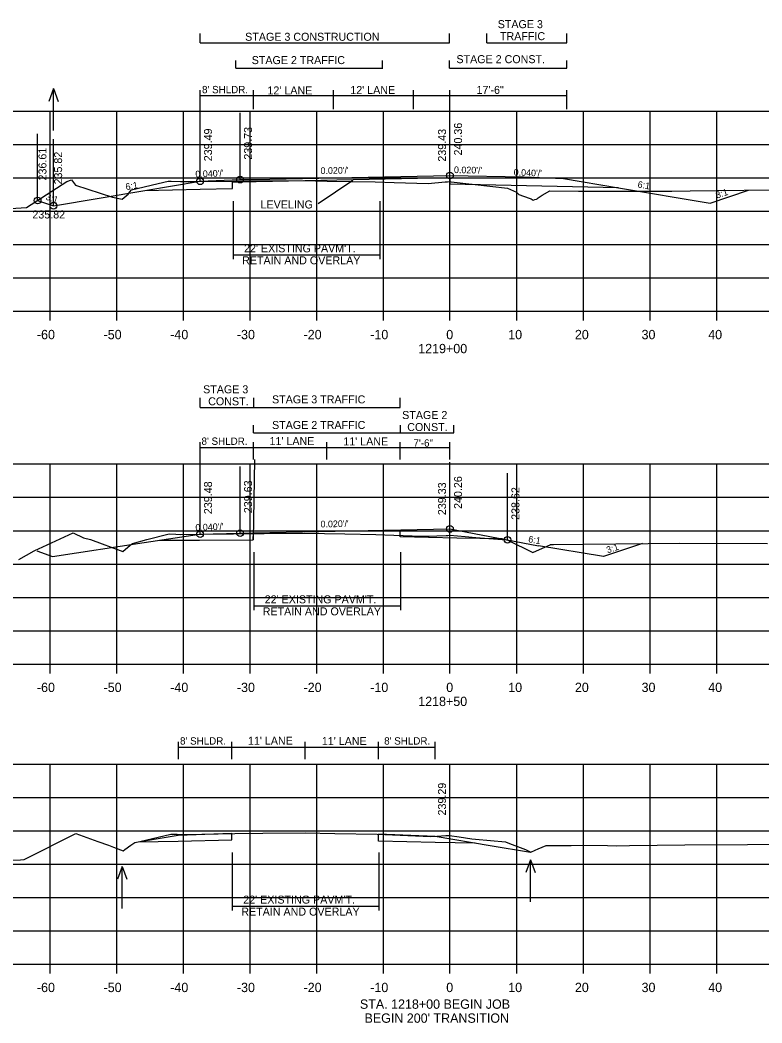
# Model space of a CAD drawing. Extents: x 1342547 to 1344156, y -1532351 to -1517216.
# Drawn here: x 1342638.4 to 1342749.7, y -1532340 to -1532189.6 of the extents above; entities that cross this region are included whole.
import ezdxf

# ---------------------------------------------------------------- set-up
doc = ezdxf.new("R2010")
doc.units = 0
for name, color, linetype in [('R_Alt Surface', 7, 'Continuous'), ('R_Axis', 7, 'Continuous'), ('R_Axis Annot', 7, 'Continuous'), ('R_Draft', 7, 'Continuous'), ('R_Exist Surface', 7, 'Continuous'), ('R_Fin Surface', 7, 'Continuous'), ('R_Grid', 7, 'Continuous'), ('R_No Plot', 7, 'Continuous'), ('R_Water', 7, 'Continuous'), ('R_Water Annot', 7, 'Continuous'), ('R_Xsect Elev', 7, 'Continuous'), ('R_Xsect Slope', 7, 'Continuous')]:
    doc.layers.add(name, color=color, linetype=linetype)

msp = doc.modelspace()

# ---------------------------------------------------------------- linework, layer by layer
at = {"layer": 'R_Alt Surface'}
for p, q in [((1342702.86, -1532213.21), (1342702.86, -1532214.21)), ((1342673.36, -1532267.52), (1342673.37, -1532266.48)), ((1342695.37, -1532267.09), (1342695.37, -1532266.04)), ((1342670.14, -1532312.53), (1342670.14, -1532311.49)), ((1342692.14, -1532312.73), (1342692.14, -1532311.68))]:
    msp.add_line(p, q, dxfattribs=at)
for points in [[(1342670.25, -1532214.86), (1342670.26, -1532213.89), (1342671.37, -1532213.84), (1342702.86, -1532213.21)], [(1342728.14, -1532214.72), (1342702.86, -1532214.21)], [(1342657.09, -1532215.13), (1342665.37, -1532214.96)], [(1342665.37, -1532214.96), (1342670.25, -1532214.86)], [(1342703.87, -1532267.26), (1342695.37, -1532267.09)], [(1342710.76, -1532267.39), (1342703.87, -1532267.26)], [(1342659.28, -1532267.58), (1342665.28, -1532267.56)], [(1342665.28, -1532267.56), (1342673.35, -1532267.52)], [(1342656.07, -1532312.82), (1342662.07, -1532312.7)], [(1342662.07, -1532312.7), (1342670.14, -1532312.53)], [(1342700.64, -1532312.9), (1342692.14, -1532312.73)], [(1342706.63, -1532313.02), (1342700.64, -1532312.9)]]:
    msp.add_lwpolyline(points, dxfattribs=at)
at = {"layer": 'R_Axis'}
for p, q in [((1342562.87, -1532233.24), (1342842.87, -1532233.24)), ((1342642.87, -1532234.64), (1342642.87, -1532233.24)), ((1342652.87, -1532234.64), (1342652.87, -1532233.24)), ((1342662.87, -1532234.64), (1342662.87, -1532233.24)), ((1342672.87, -1532234.64), (1342672.87, -1532233.24)), ((1342682.87, -1532234.64), (1342682.87, -1532233.24)), ((1342692.87, -1532234.64), (1342692.87, -1532233.24)), ((1342702.86, -1532234.64), (1342702.86, -1532233.24)), ((1342712.87, -1532234.64), (1342712.87, -1532233.24)), ((1342722.87, -1532234.64), (1342722.87, -1532233.24)), ((1342732.87, -1532234.64), (1342732.87, -1532233.24)), ((1342742.87, -1532234.64), (1342742.87, -1532233.24)), ((1342562.87, -1532286.15), (1342842.87, -1532286.15)), ((1342642.87, -1532287.55), (1342642.87, -1532286.15)), ((1342652.87, -1532287.55), (1342652.87, -1532286.15)), ((1342662.87, -1532287.55), (1342662.87, -1532286.15)), ((1342672.87, -1532287.55), (1342672.87, -1532286.15)), ((1342682.87, -1532287.55), (1342682.87, -1532286.15)), ((1342692.87, -1532287.55), (1342692.87, -1532286.15)), ((1342702.86, -1532287.55), (1342702.86, -1532286.15)), ((1342712.87, -1532287.55), (1342712.87, -1532286.15)), ((1342722.87, -1532287.55), (1342722.87, -1532286.15)), ((1342732.87, -1532287.55), (1342732.87, -1532286.15)), ((1342742.87, -1532287.55), (1342742.87, -1532286.15)), ((1342562.87, -1532331.15), (1342842.87, -1532331.15)), ((1342642.87, -1532332.55), (1342642.87, -1532331.15)), ((1342652.87, -1532332.55), (1342652.87, -1532331.15)), ((1342662.87, -1532332.55), (1342662.87, -1532331.15)), ((1342672.87, -1532332.55), (1342672.87, -1532331.15)), ((1342682.87, -1532332.55), (1342682.87, -1532331.15)), ((1342692.87, -1532332.55), (1342692.87, -1532331.15)), ((1342702.86, -1532332.55), (1342702.86, -1532331.15)), ((1342712.87, -1532332.55), (1342712.87, -1532331.15)), ((1342722.87, -1532332.55), (1342722.87, -1532331.15)), ((1342732.87, -1532332.55), (1342732.87, -1532331.15)), ((1342742.87, -1532332.55), (1342742.87, -1532331.15))]:
    msp.add_line(p, q, dxfattribs=at)
at = {"layer": 'R_Draft'}
for p, q in [((1342665.37, -1532193.01), (1342665.37, -1532191.58)), ((1342702.78, -1532193.01), (1342702.78, -1532191.58)), ((1342708.37, -1532193.01), (1342708.37, -1532191.58)), ((1342720.37, -1532193.01), (1342720.37, -1532191.58)), ((1342665.37, -1532193.01), (1342702.78, -1532193.01)), ((1342708.37, -1532193.01), (1342720.37, -1532193.01)), ((1342670.72, -1532196.8), (1342670.72, -1532195.66)), ((1342692.72, -1532196.9), (1342692.72, -1532195.66)), ((1342702.78, -1532196.8), (1342702.78, -1532195.66)), ((1342720.37, -1532196.8), (1342720.37, -1532195.66)), ((1342670.72, -1532196.8), (1342692.72, -1532196.8)), ((1342702.78, -1532196.8), (1342720.37, -1532196.8)), ((1342670.33, -1532216.73), (1342670.33, -1532225.45)), ((1342692.33, -1532216.73), (1342692.33, -1532225.45)), ((1342670.33, -1532224.78), (1342692.33, -1532224.78)), ((1342665.37, -1532247.67), (1342665.37, -1532246.24)), ((1342665.37, -1532247.67), (1342695.37, -1532247.67)), ((1342673.37, -1532246.24), (1342673.37, -1532247.67)), ((1342695.37, -1532247.67), (1342695.37, -1532246.24)), ((1342673.37, -1532251.47), (1342673.37, -1532250.33)), ((1342695.37, -1532250.33), (1342695.37, -1532251.47)), ((1342703.42, -1532251.47), (1342703.42, -1532250.33)), ((1342673.37, -1532251.47), (1342692.72, -1532251.47)), ((1342685.84, -1532251.47), (1342703.42, -1532251.47)), ((1342673.42, -1532269.37), (1342673.42, -1532278.09)), ((1342695.43, -1532269.37), (1342695.43, -1532278.09)), ((1342673.42, -1532277.41), (1342695.43, -1532277.41)), ((1342670.21, -1532314.4), (1342670.21, -1532323.12)), ((1342692.21, -1532314.4), (1342692.21, -1532323.12)), ((1342670.21, -1532322.45), (1342692.21, -1532322.45))]:
    msp.add_line(p, q, dxfattribs=at)
at = {"layer": 'R_Exist Surface'}
for points in [[(1342630.56, -1532218.22), (1342639.35, -1532217.69), (1342645.4, -1532213.8), (1342646.08, -1532213.54), (1342646.71, -1532214.35), (1342652.22, -1532216.14), (1342653.69, -1532216.43), (1342654.61, -1532215.7), (1342654.82, -1532215.32), (1342655.11, -1532215.03), (1342659.94, -1532213.91), (1342660.6, -1532213.73), (1342661.04, -1532213.75), (1342662.43, -1532213.8), (1342664.72, -1532213.78), (1342670.26, -1532213.73), (1342673.46, -1532213.71), (1342680.93, -1532213.66), (1342684.43, -1532213.73), (1342691.64, -1532213.85), (1342694.48, -1532213.93), (1342699.59, -1532214.08), (1342702.15, -1532213.86), (1342702.5, -1532213.83), (1342702.85, -1532213.81), (1342703.06, -1532213.83), (1342706.15, -1532214.18), (1342706.21, -1532214.19), (1342711.48, -1532214.78), (1342712.83, -1532215.4), (1342713.2, -1532215.74), (1342714.75, -1532216.28), (1342715.02, -1532216.39), (1342715.35, -1532216.58), (1342715.6, -1532216.46), (1342715.82, -1532216.42), (1342715.94, -1532216.37), (1342716.07, -1532216.22), (1342716.7, -1532215.85), (1342717.82, -1532215.17), (1342722.13, -1532215.24), (1342723.02, -1532215.26), (1342724.92, -1532215.23), (1342736.14, -1532215.22), (1342738.91, -1532215.19), (1342755.04, -1532214.99)], [(1342638.19, -1532270.45), (1342640.47, -1532269.19), (1342646.32, -1532266.45), (1342647.89, -1532267.2), (1342648.93, -1532267.47), (1342653.8, -1532269.26), (1342654.9, -1532268.33), (1342655.22, -1532268.06), (1342657.4, -1532267.49), (1342660.76, -1532266.64), (1342661.76, -1532266.68), (1342662.47, -1532266.71), (1342665.87, -1532266.67), (1342670.38, -1532266.6), (1342674.98, -1532266.57), (1342680.99, -1532266.53), (1342687.1, -1532266.64), (1342691.75, -1532266.72), (1342698.55, -1532266.95), (1342699.74, -1532266.99), (1342700.88, -1532266.93), (1342702.28, -1532266.86), (1342702.52, -1532266.85), (1342702.86, -1532266.82), (1342705.16, -1532267.04), (1342706.73, -1532267.19), (1342711.36, -1532267.52), (1342711.48, -1532267.53), (1342711.55, -1532267.56), (1342715.27, -1532269.44), (1342716.75, -1532268.76), (1342717.88, -1532268.27), (1342717.96, -1532268.22), (1342718.41, -1532268.22), (1342722.84, -1532268.18), (1342732.58, -1532268.07), (1342737.25, -1532268), (1342750.5, -1532268.05)], [(1342629.07, -1532315.88), (1342638.45, -1532315.51), (1342639.01, -1532315.48), (1342639.41, -1532315.27), (1342646.76, -1532311.58), (1342650.04, -1532312.75), (1342651.65, -1532313.31), (1342652.39, -1532313.63), (1342653.82, -1532314.16), (1342654.07, -1532313.94), (1342654.99, -1532313.33), (1342655.6, -1532312.93), (1342656.33, -1532312.76), (1342660.98, -1532311.67), (1342661.93, -1532311.68), (1342662.64, -1532311.71), (1342665.63, -1532311.65), (1342670.58, -1532311.54), (1342674.77, -1532311.51), (1342681.14, -1532311.47), (1342685.57, -1532311.55), (1342691.94, -1532311.67), (1342698.86, -1532311.95), (1342699.98, -1532312), (1342700.89, -1532311.95), (1342702.22, -1532311.88), (1342702.45, -1532311.86), (1342702.8, -1532311.85), (1342704.25, -1532312.06), (1342706.14, -1532312.36), (1342706.68, -1532312.4), (1342711.17, -1532312.79), (1342711.81, -1532313.05), (1342714.18, -1532313.97), (1342714.97, -1532314.37), (1342715.64, -1532314.06), (1342716.11, -1532313.88), (1342717.29, -1532313.36), (1342721.04, -1532313.35), (1342722.78, -1532313.33), (1342726.49, -1532313.37), (1342727.84, -1532313.39), (1342729.77, -1532313.36), (1342738.09, -1532313.27), (1342747.47, -1532313.2), (1342754.83, -1532313.14)]]:
    msp.add_lwpolyline(points, dxfattribs=at)
at = {"layer": 'R_Fin Surface'}
for p, q in [((1342673.37, -1532213.47), (1342702.86, -1532212.88)), ((1342702.86, -1532212.88), (1342713.87, -1532213.1)), ((1342713.87, -1532213.1), (1342719.87, -1532213.34)), ((1342657.09, -1532215.13), (1342665.37, -1532213.75)), ((1342665.37, -1532213.75), (1342671.37, -1532213.51)), ((1342671.37, -1532213.51), (1342673.37, -1532213.47)), ((1342719.87, -1532213.34), (1342728.14, -1532214.72)), ((1342643.37, -1532217.42), (1342657.09, -1532215.13)), ((1342728.14, -1532214.72), (1342741.87, -1532217.01)), ((1342741.87, -1532217.01), (1342747.64, -1532215.08)), ((1342641.01, -1532216.63), (1342643.37, -1532217.42))]:
    msp.add_line(p, q, dxfattribs=at)
for points in [[(1342640.9, -1532269.19), (1342643.24, -1532270.01), (1342657, -1532267.93), (1342665.3, -1532266.68), (1342673.37, -1532266.48)], [(1342665.37, -1532266.67), (1342671.37, -1532266.52), (1342673.37, -1532266.48), (1342702.86, -1532265.89), (1342716.12, -1532268.42)], [(1342731.75, -1532268.08), (1342725.87, -1532270.04), (1342716.12, -1532268.42)], [(1342656.07, -1532312.82), (1342662.07, -1532311.82), (1342670.14, -1532311.49)], [(1342714.96, -1532314.4), (1342708.91, -1532313.4), (1342700.64, -1532312.02), (1342692.14, -1532311.68)]]:
    msp.add_lwpolyline(points, dxfattribs=at)
at = {"layer": 'R_Grid'}
for p, q in [((1342562.87, -1532203.24), (1342842.87, -1532203.24)), ((1342642.87, -1532233.24), (1342642.87, -1532203.24)), ((1342652.87, -1532233.24), (1342652.87, -1532203.24)), ((1342662.87, -1532233.24), (1342662.87, -1532203.24)), ((1342672.87, -1532233.24), (1342672.87, -1532203.24)), ((1342682.87, -1532233.24), (1342682.87, -1532203.24)), ((1342692.87, -1532233.24), (1342692.87, -1532203.24)), ((1342702.86, -1532233.24), (1342702.86, -1532203.24)), ((1342712.87, -1532233.24), (1342712.87, -1532203.24)), ((1342722.87, -1532233.24), (1342722.87, -1532203.24)), ((1342732.87, -1532233.24), (1342732.87, -1532203.24)), ((1342742.87, -1532233.24), (1342742.87, -1532203.24)), ((1342562.87, -1532208.24), (1342842.87, -1532208.24)), ((1342562.87, -1532213.24), (1342842.87, -1532213.24)), ((1342562.87, -1532218.24), (1342842.87, -1532218.24)), ((1342562.87, -1532223.24), (1342842.87, -1532223.24)), ((1342562.87, -1532228.24), (1342842.87, -1532228.24)), ((1342562.87, -1532233.24), (1342842.87, -1532233.24)), ((1342562.87, -1532256.15), (1342842.87, -1532256.15)), ((1342642.87, -1532286.15), (1342642.87, -1532256.15)), ((1342652.87, -1532286.15), (1342652.87, -1532256.15)), ((1342662.87, -1532286.15), (1342662.87, -1532256.15)), ((1342672.87, -1532286.15), (1342672.87, -1532256.15)), ((1342682.87, -1532286.15), (1342682.87, -1532256.15)), ((1342692.87, -1532286.15), (1342692.87, -1532256.15)), ((1342702.86, -1532286.15), (1342702.86, -1532256.15)), ((1342712.87, -1532286.15), (1342712.87, -1532256.15)), ((1342722.87, -1532286.15), (1342722.87, -1532256.15)), ((1342732.87, -1532286.15), (1342732.87, -1532256.15)), ((1342742.87, -1532286.15), (1342742.87, -1532256.15)), ((1342562.87, -1532261.15), (1342842.87, -1532261.15)), ((1342562.87, -1532266.15), (1342842.87, -1532266.15)), ((1342562.87, -1532271.15), (1342842.87, -1532271.15)), ((1342562.87, -1532276.15), (1342842.87, -1532276.15)), ((1342562.87, -1532281.15), (1342842.87, -1532281.15)), ((1342562.87, -1532286.15), (1342842.87, -1532286.15)), ((1342562.87, -1532301.15), (1342842.87, -1532301.15)), ((1342642.87, -1532331.15), (1342642.87, -1532301.15)), ((1342652.87, -1532331.15), (1342652.87, -1532301.15)), ((1342662.87, -1532331.15), (1342662.87, -1532301.15)), ((1342672.87, -1532331.15), (1342672.87, -1532301.15)), ((1342682.87, -1532331.15), (1342682.87, -1532301.15)), ((1342692.87, -1532331.15), (1342692.87, -1532301.15)), ((1342702.86, -1532331.15), (1342702.86, -1532301.15)), ((1342712.87, -1532331.15), (1342712.87, -1532301.15)), ((1342722.87, -1532331.15), (1342722.87, -1532301.15)), ((1342732.87, -1532331.15), (1342732.87, -1532301.15)), ((1342742.87, -1532331.15), (1342742.87, -1532301.15)), ((1342562.87, -1532306.15), (1342842.87, -1532306.15)), ((1342562.87, -1532311.15), (1342842.87, -1532311.15)), ((1342562.87, -1532316.15), (1342842.87, -1532316.15)), ((1342562.87, -1532321.15), (1342842.87, -1532321.15)), ((1342562.87, -1532326.15), (1342842.87, -1532326.15)), ((1342562.87, -1532331.15), (1342842.87, -1532331.15))]:
    msp.add_line(p, q, dxfattribs=at)
at = {"layer": 'R_No Plot'}
for centre in [(1342671.37, -1532213.51), (1342671.37, -1532213.51), (1342702.86, -1532212.88), (1342702.86, -1532212.88), (1342665.37, -1532213.75), (1342665.37, -1532213.75), (1342641.01, -1532216.63), (1342641.01, -1532216.63), (1342643.37, -1532217.42), (1342643.37, -1532217.42), (1342702.86, -1532265.89), (1342702.86, -1532265.89), (1342665.37, -1532266.67), (1342665.37, -1532266.67), (1342671.37, -1532266.52), (1342671.37, -1532266.52), (1342711.48, -1532267.53), (1342711.48, -1532267.53)]:
    msp.add_circle(centre, 0.5, dxfattribs=at)
at = {"layer": 'R_Water'}
for p, q in [((1342643.39, -1532199.85), (1342642.69, -1532201.78)), ((1342643.39, -1532206.14), (1342643.39, -1532199.85)), ((1342643.39, -1532199.85), (1342644.09, -1532201.78)), ((1342653.68, -1532316.51), (1342652.98, -1532318.43)), ((1342653.68, -1532322.79), (1342653.68, -1532316.51)), ((1342653.68, -1532316.51), (1342654.38, -1532318.43)), ((1342714.94, -1532315.51), (1342714.24, -1532317.43)), ((1342714.94, -1532321.79), (1342714.94, -1532315.51)), ((1342714.94, -1532315.51), (1342715.64, -1532317.43))]:
    msp.add_line(p, q, dxfattribs=at)
at = {"layer": 'R_Xsect Elev'}
for p, q in [((1342665.37, -1532213.34), (1342665.37, -1532200.08)), ((1342720.37, -1532200.94), (1342665.37, -1532200.94)), ((1342673.37, -1532202.95), (1342673.37, -1532200.08)), ((1342685.37, -1532202.95), (1342685.37, -1532200.08)), ((1342697.37, -1532202.95), (1342697.37, -1532200.08)), ((1342702.86, -1532202.95), (1342702.86, -1532200.08)), ((1342720.37, -1532202.95), (1342720.37, -1532200.08)), ((1342665.37, -1532213.75), (1342665.37, -1532203.75)), ((1342665.37, -1532213.75), (1342665.37, -1532203.75)), ((1342671.37, -1532213.51), (1342671.37, -1532203.51)), ((1342702.86, -1532212.88), (1342702.86, -1532202.88)), ((1342702.86, -1532213.81), (1342702.86, -1532203.81)), ((1342641.01, -1532216.63), (1342641.01, -1532206.63)), ((1342643.37, -1532217.42), (1342643.37, -1532207.42)), ((1342688.29, -1532213.64), (1342683.09, -1532217.12)), ((1342665.37, -1532266.14), (1342665.37, -1532252.89)), ((1342702.86, -1532253.74), (1342665.37, -1532253.74)), ((1342673.37, -1532255.47), (1342673.37, -1532252.89)), ((1342684.37, -1532255.47), (1342684.37, -1532252.89)), ((1342695.37, -1532255.47), (1342695.37, -1532252.89)), ((1342702.86, -1532255.47), (1342702.86, -1532252.89)), ((1342665.37, -1532266.67), (1342665.37, -1532256.67)), ((1342665.37, -1532266.67), (1342665.37, -1532256.67)), ((1342671.37, -1532266.52), (1342671.37, -1532256.52)), ((1342673.53, -1532255.47), (1342673.35, -1532267.5)), ((1342702.86, -1532265.89), (1342702.86, -1532255.89)), ((1342702.86, -1532266.82), (1342702.86, -1532256.82)), ((1342711.48, -1532267.53), (1342711.48, -1532257.53)), ((1342662.14, -1532300.41), (1342662.14, -1532297.83)), ((1342700.64, -1532298.69), (1342662.14, -1532298.69)), ((1342670.14, -1532300.41), (1342670.14, -1532297.83)), ((1342681.14, -1532300.41), (1342681.14, -1532297.83)), ((1342692.14, -1532300.41), (1342692.14, -1532297.83)), ((1342700.64, -1532300.41), (1342700.64, -1532297.83)), ((1342702.86, -1532311.86), (1342702.86, -1532301.86))]:
    msp.add_line(p, q, dxfattribs=at)

# ---------------------------------------------------------------- texts
at = {"layer": 'R_Axis Annot'}
for s, p in [('-60', (1342640.9, -1532237.44)), ('-50', (1342650.9, -1532237.44)), ('-40', (1342660.9, -1532237.44)), ('-30', (1342670.9, -1532237.44)), ('-20', (1342680.9, -1532237.44)), ('-10', (1342690.9, -1532237.44)), ('0', (1342702.3, -1532237.44)), ('10', (1342711.6, -1532237.44)), ('20', (1342721.6, -1532237.44)), ('30', (1342731.6, -1532237.44)), ('40', (1342741.6, -1532237.44)), ('1219+00', (1342698.1, -1532239.54)), ('-60', (1342640.9, -1532290.35)), ('-50', (1342650.9, -1532290.35)), ('-40', (1342660.9, -1532290.35)), ('-30', (1342670.9, -1532290.35)), ('-20', (1342680.9, -1532290.35)), ('-10', (1342690.9, -1532290.35)), ('0', (1342702.3, -1532290.35)), ('10', (1342711.6, -1532290.35)), ('20', (1342721.6, -1532290.35)), ('30', (1342731.6, -1532290.35)), ('40', (1342741.6, -1532290.35)), ('1218+50', (1342698.1, -1532292.45)), ('-60', (1342640.9, -1532335.35)), ('-50', (1342650.9, -1532335.35)), ('-40', (1342660.9, -1532335.35)), ('-30', (1342670.9, -1532335.35)), ('-20', (1342680.9, -1532335.35)), ('-10', (1342690.9, -1532335.35)), ('0', (1342702.3, -1532335.35)), ('10', (1342711.6, -1532335.35)), ('20', (1342721.6, -1532335.35)), ('30', (1342731.6, -1532335.35)), ('40', (1342741.6, -1532335.35)), ('STA. 1218+00 BEGIN JOB', (1342689.35, -1532337.85)), ("BEGIN 200' TRANSITION", (1342690.04, -1532339.95))]:
    msp.add_text(s, height=1.4, dxfattribs=at).set_placement(p)
at = {"layer": 'R_Draft'}
for s, p in [('STAGE 3', (1342710.02, -1532190.79)), ('STAGE 3 CONSTRUCTION', (1342672.14, -1532192.68)), ('TRAFFIC', (1342710.36, -1532192.59)), ('STAGE 2 TRAFFIC', (1342673.12, -1532196.18)), ('STAGE 2 CONST.', (1342703.83, -1532196.04)), ("22' EXISTING PAVM'T.", (1342671.97, -1532224.41)), ('RETAIN AND OVERLAY', (1342671.68, -1532226.21)), ('STAGE 3', (1342665.83, -1532245.55)), ('CONST.', (1342666.59, -1532247.35)), ('STAGE 3 TRAFFIC', (1342676.17, -1532247.06)), ('STAGE 2', (1342695.69, -1532249.41)), ('STAGE 2 TRAFFIC', (1342676.17, -1532250.9)), ('CONST.', (1342696.45, -1532251.21)), ("22' EXISTING PAVM'T.", (1342675.07, -1532277.05)), ('RETAIN AND OVERLAY', (1342674.77, -1532278.85)), ("22' EXISTING PAVM'T.", (1342671.85, -1532322.08)), ('RETAIN AND OVERLAY', (1342671.56, -1532323.88))]:
    msp.add_text(s, height=1.2, dxfattribs=at).set_placement(p)
at = {"layer": 'R_Water Annot'}
msp.add_text('235.82', height=1.2, dxfattribs=at).set_placement((1342640.22, -1532219.33))
msp.add_text('235.82', height=1.2, dxfattribs=at).set_placement((1342640.22, -1532219.33))
at = {"layer": 'R_Xsect Elev'}
for s, height, p in [("8' SHLDR.", 1.1, (1342665.67, -1532200.55)), ("12' LANE", 1.2, (1342675.48, -1532200.73)), ("12' LANE", 1.2, (1342687.91, -1532200.67)), ('17\'-6"', 1.2, (1342706.84, -1532200.65)), ('LEVELING', 1.2, (1342674.45, -1532217.83)), ("8' SHLDR.", 1.1, (1342665.59, -1532253.28)), ("11' LANE", 1.2, (1342675.79, -1532253.31)), ("11' LANE", 1.2, (1342686.86, -1532253.36)), ('7\'-6"', 1.1, (1342697.38, -1532253.55)), ("8' SHLDR.", 1.1, (1342662.37, -1532298.23)), ("11' LANE", 1.2, (1342672.56, -1532298.25)), ("11' LANE", 1.2, (1342683.64, -1532298.3)), ("8' SHLDR.", 1.1, (1342692.99, -1532298.23))]:
    msp.add_text(s, height=height, dxfattribs=at).set_placement(p)
for s, p in [('240.36', (1342704.67, -1532209.88)), ('239.49', (1342667.17, -1532210.75)), ('239.73', (1342673.17, -1532210.51)), ('239.43', (1342702.27, -1532210.81)), ('236.61', (1342642.33, -1532213.63)), ('235.82', (1342644.68, -1532214.23)), ('240.26', (1342704.67, -1532262.89)), ('239.48', (1342667.17, -1532263.67)), ('239.63', (1342673.17, -1532263.52)), ('239.33', (1342702.27, -1532263.82)), ('238.62', (1342713.28, -1532264.53)), ('239.29', (1342702.27, -1532308.86))]:
    msp.add_text(s, height=1.2, rotation=90, dxfattribs=at).set_placement(p)
at = {"layer": 'R_Xsect Slope'}
for s, rotation, p in [("0.020'/'", 1.1458, (1342683.45, -1532212.67)), ("0.020'/'", 358.8542, (1342703.45, -1532212.52)), ("0.040'/'", 2.2906, (1342664.69, -1532213.18)), ("0.040'/'", 357.7094, (1342712.4, -1532212.88)), ('6:1', 9.4623, (1342654.28, -1532215.09)), ('6:1', 350.5377, (1342730.95, -1532214.68)), ('3:1', 341.5651, (1342642.13, -1532216.48)), ('3:1', 18.4349, (1342742.9, -1532216.36)), ("0.040'/'", 2.2906, (1342664.69, -1532266.18)), ("0.020'/'", 1.1458, (1342683.45, -1532265.67)), ('6:1', 350.5377, (1342714.55, -1532267.88)), ('3:1', 18.4349, (1342726.51, -1532269.56))]:
    msp.add_text(s, height=1, rotation=rotation, dxfattribs=at).set_placement(p)

doc.saveas('drawing.dxf')
